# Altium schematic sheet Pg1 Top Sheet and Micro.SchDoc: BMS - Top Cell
size Letter; Organization: Kettering University; Address1: EV Kartz; Address2: Battery; Address3: Flint, MI; Address4: United States of America; DocumentNumber: 1; Revision: 1; SheetNumber: 1; SheetTotal: 1
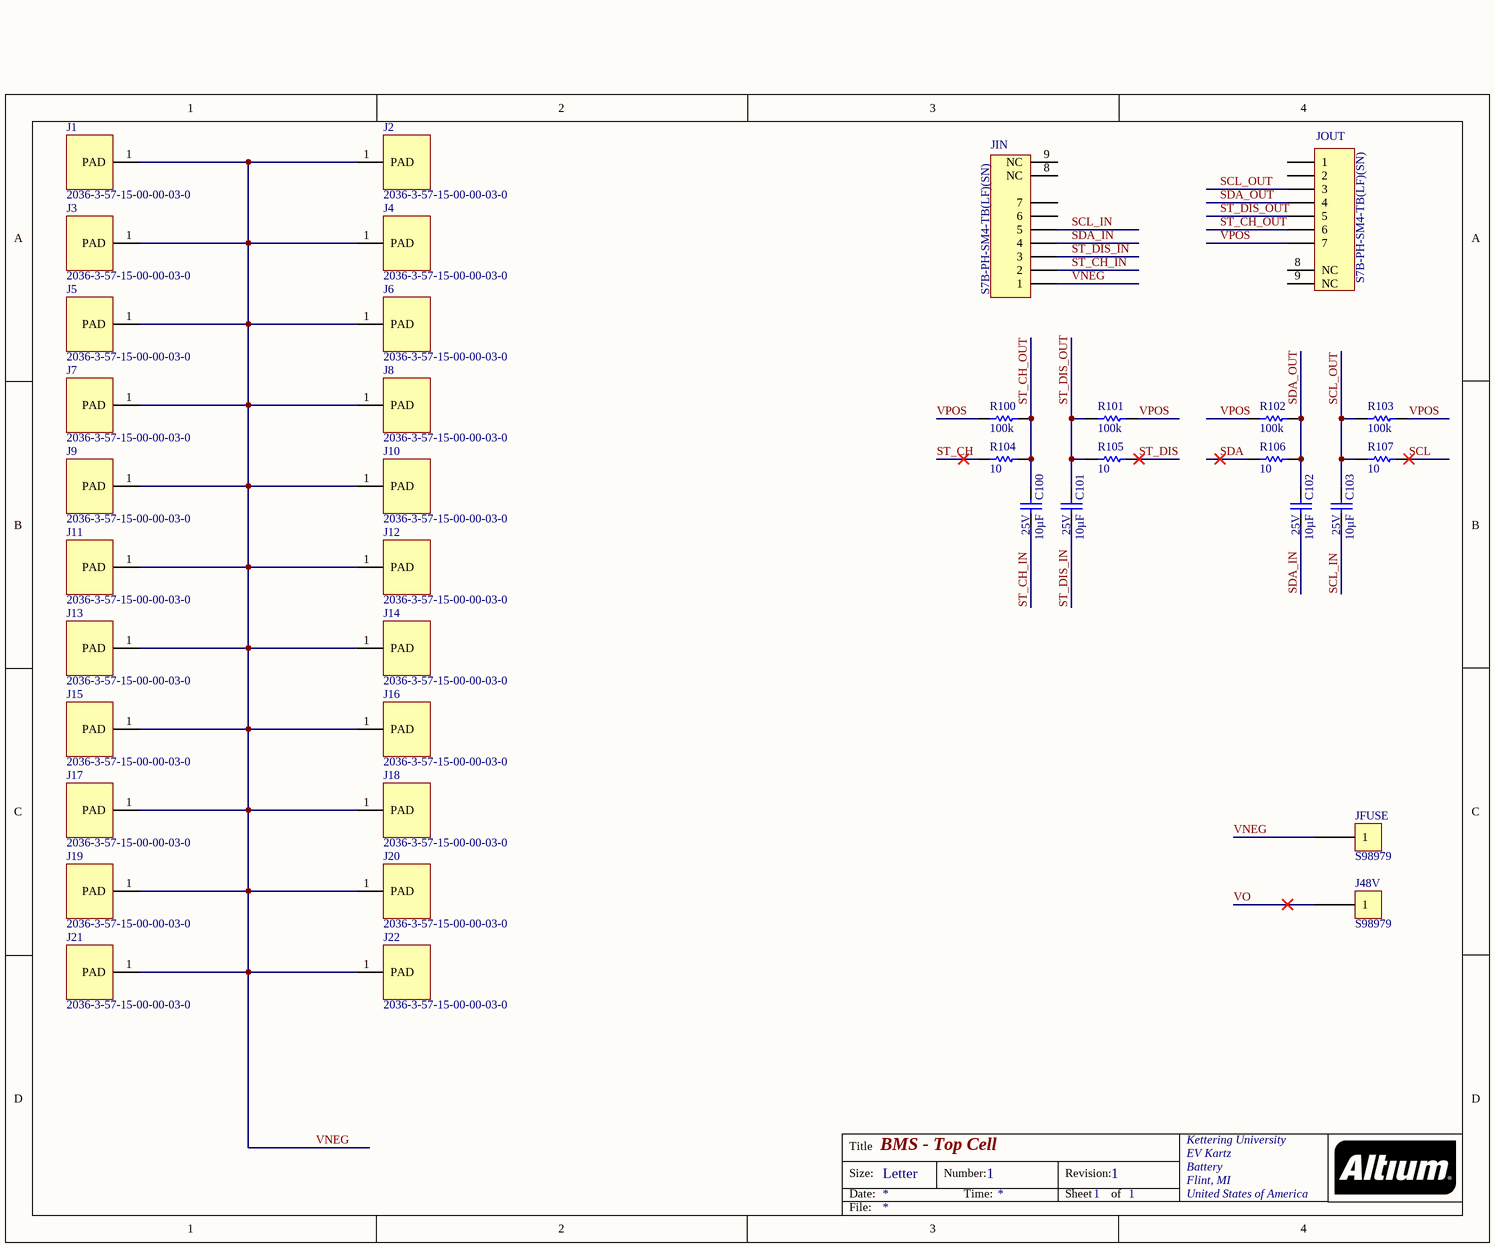
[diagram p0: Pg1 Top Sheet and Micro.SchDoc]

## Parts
C100  value 10µF  Rated: 25V  [CAPC3225N]  (hidden comment: C1210C106K3RACAUTO)
C101  value 10µF  Rated: 25V  [CAPC3225N]  (hidden comment: C1210C106K3RACAUTO)
C102  value 10µF  Rated: 25V  [CAPC3225N]  (hidden comment: C1210C106K3RACAUTO)
C103  value 10µF  Rated: 25V  [CAPC3225N]  (hidden comment: C1210C106K3RACAUTO)
J1  2036-3-57-15-00-00-03-0  [6mm Pad]
J2  2036-3-57-15-00-00-03-0  [6mm Pad]
J3  2036-3-57-15-00-00-03-0  [6mm Pad]
J4  2036-3-57-15-00-00-03-0  [6mm Pad]
J5  2036-3-57-15-00-00-03-0  [6mm Pad]
J6  2036-3-57-15-00-00-03-0  [6mm Pad]
J7  2036-3-57-15-00-00-03-0  [6mm Pad]
J8  2036-3-57-15-00-00-03-0  [6mm Pad]
J9  2036-3-57-15-00-00-03-0  [6mm Pad]
J10  2036-3-57-15-00-00-03-0  [6mm Pad]
J11  2036-3-57-15-00-00-03-0  [6mm Pad]
J12  2036-3-57-15-00-00-03-0  [6mm Pad]
J13  2036-3-57-15-00-00-03-0  [6mm Pad]
J14  2036-3-57-15-00-00-03-0  [6mm Pad]
J15  2036-3-57-15-00-00-03-0  [6mm Pad]
J16  2036-3-57-15-00-00-03-0  [6mm Pad]
J17  2036-3-57-15-00-00-03-0  [6mm Pad]
J18  2036-3-57-15-00-00-03-0  [6mm Pad]
J19  2036-3-57-15-00-00-03-0  [6mm Pad]
J20  2036-3-57-15-00-00-03-0  [6mm Pad]
J21  2036-3-57-15-00-00-03-0  [6mm Pad]
J22  2036-3-57-15-00-00-03-0  [6mm Pad]
J48V  S98979  [S98979]
JFUSE  S98979  [S98979]
JIN  S7B-PH-SM4-TB(LF)(SN)  [JST-PH-S7]
JOUT  S7B-PH-SM4-TB(LF)(SN)  [JST-PH-S7]
R100  value 100k  [RESC2012N]  (hidden comment: ERJ-6ENF1003V)
R101  value 100k  [RESC2012N]  (hidden comment: ERJ-6ENF1003V)
R102  value 100k  [RESC2012N]  (hidden comment: ERJ-6ENF1003V)
R103  value 100k  [RESC2012N]  (hidden comment: ERJ-6ENF1003V)
R104  value 10  [RESC2012N]  (hidden comment: ERJ-6ENF10R0V)
R105  value 10  [RESC2012N]  (hidden comment: ERJ-6ENF10R0V)
R106  value 10  [RESC2012N]  (hidden comment: ERJ-6ENF10R0V)
R107  value 10  [RESC2012N]  (hidden comment: ERJ-6ENF10R0V)

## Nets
SCL: R107.2
SCL_IN: C103.1 JIN.5
SCL_OUT: C103.2 JOUT.3 R103.2 R107.1
SDA: R106.1
SDA_IN: C102.1 JIN.4
SDA_OUT: C102.2 JOUT.4 R102.1 R106.2
ST_CH: R104.1
ST_CH_IN: C100.1 JIN.2
ST_CH_OUT: C100.2 JOUT.6 R100.1 R104.2
ST_DIS: R105.2
ST_DIS_IN: C101.1 JIN.3
ST_DIS_OUT: C101.2 JOUT.5 R101.2 R105.1
VNEG: J1.1(PAD) J2.1(PAD) J3.1(PAD) J4.1(PAD) J5.1(PAD) J6.1(PAD) J7.1(PAD) J8.1(PAD) J9.1(PAD) J10.1(PAD) J11.1(PAD) J12.1(PAD) J13.1(PAD) J14.1(PAD) J15.1(PAD) J16.1(PAD) J17.1(PAD) J18.1(PAD) J19.1(PAD) J20.1(PAD) J21.1(PAD) J22.1(PAD) JFUSE.1 JIN.1
VO: J48V.1
VPOS: JOUT.7 R100.2 R101.1 R102.2 R103.1

Not connected (* = marked no-connect by the designer): JIN 6 7 8(NC) 9(NC); JOUT 1 2 8(NC) 9(NC)

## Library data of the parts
C100-C103 = C1210C106K3RACAUTO: Capacitor, Ceramic, 10µF, 25V, 0805, 10%, 125C
J1-J22 = 2036-3-57-15-00-00-03-0: Hardware, Sprint Contact Surface
J48V JFUSE = S98979: Screw Terminal M8, 360A
JIN JOUT = S7B-PH-SM4-TB(LF)(SN): Header, JST, 7-Pin, Right-Angle, PH, Surface Mount
R100-R103 = ERJ-6ENF1003V: Resistor, Fixed, 100 kOhm, 0805, 1%, 1/8W
R104-R107 = ERJ-6ENF10R0V: Resistor, Fixed, 10 Ohm, 0805, 1%, 1/8W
